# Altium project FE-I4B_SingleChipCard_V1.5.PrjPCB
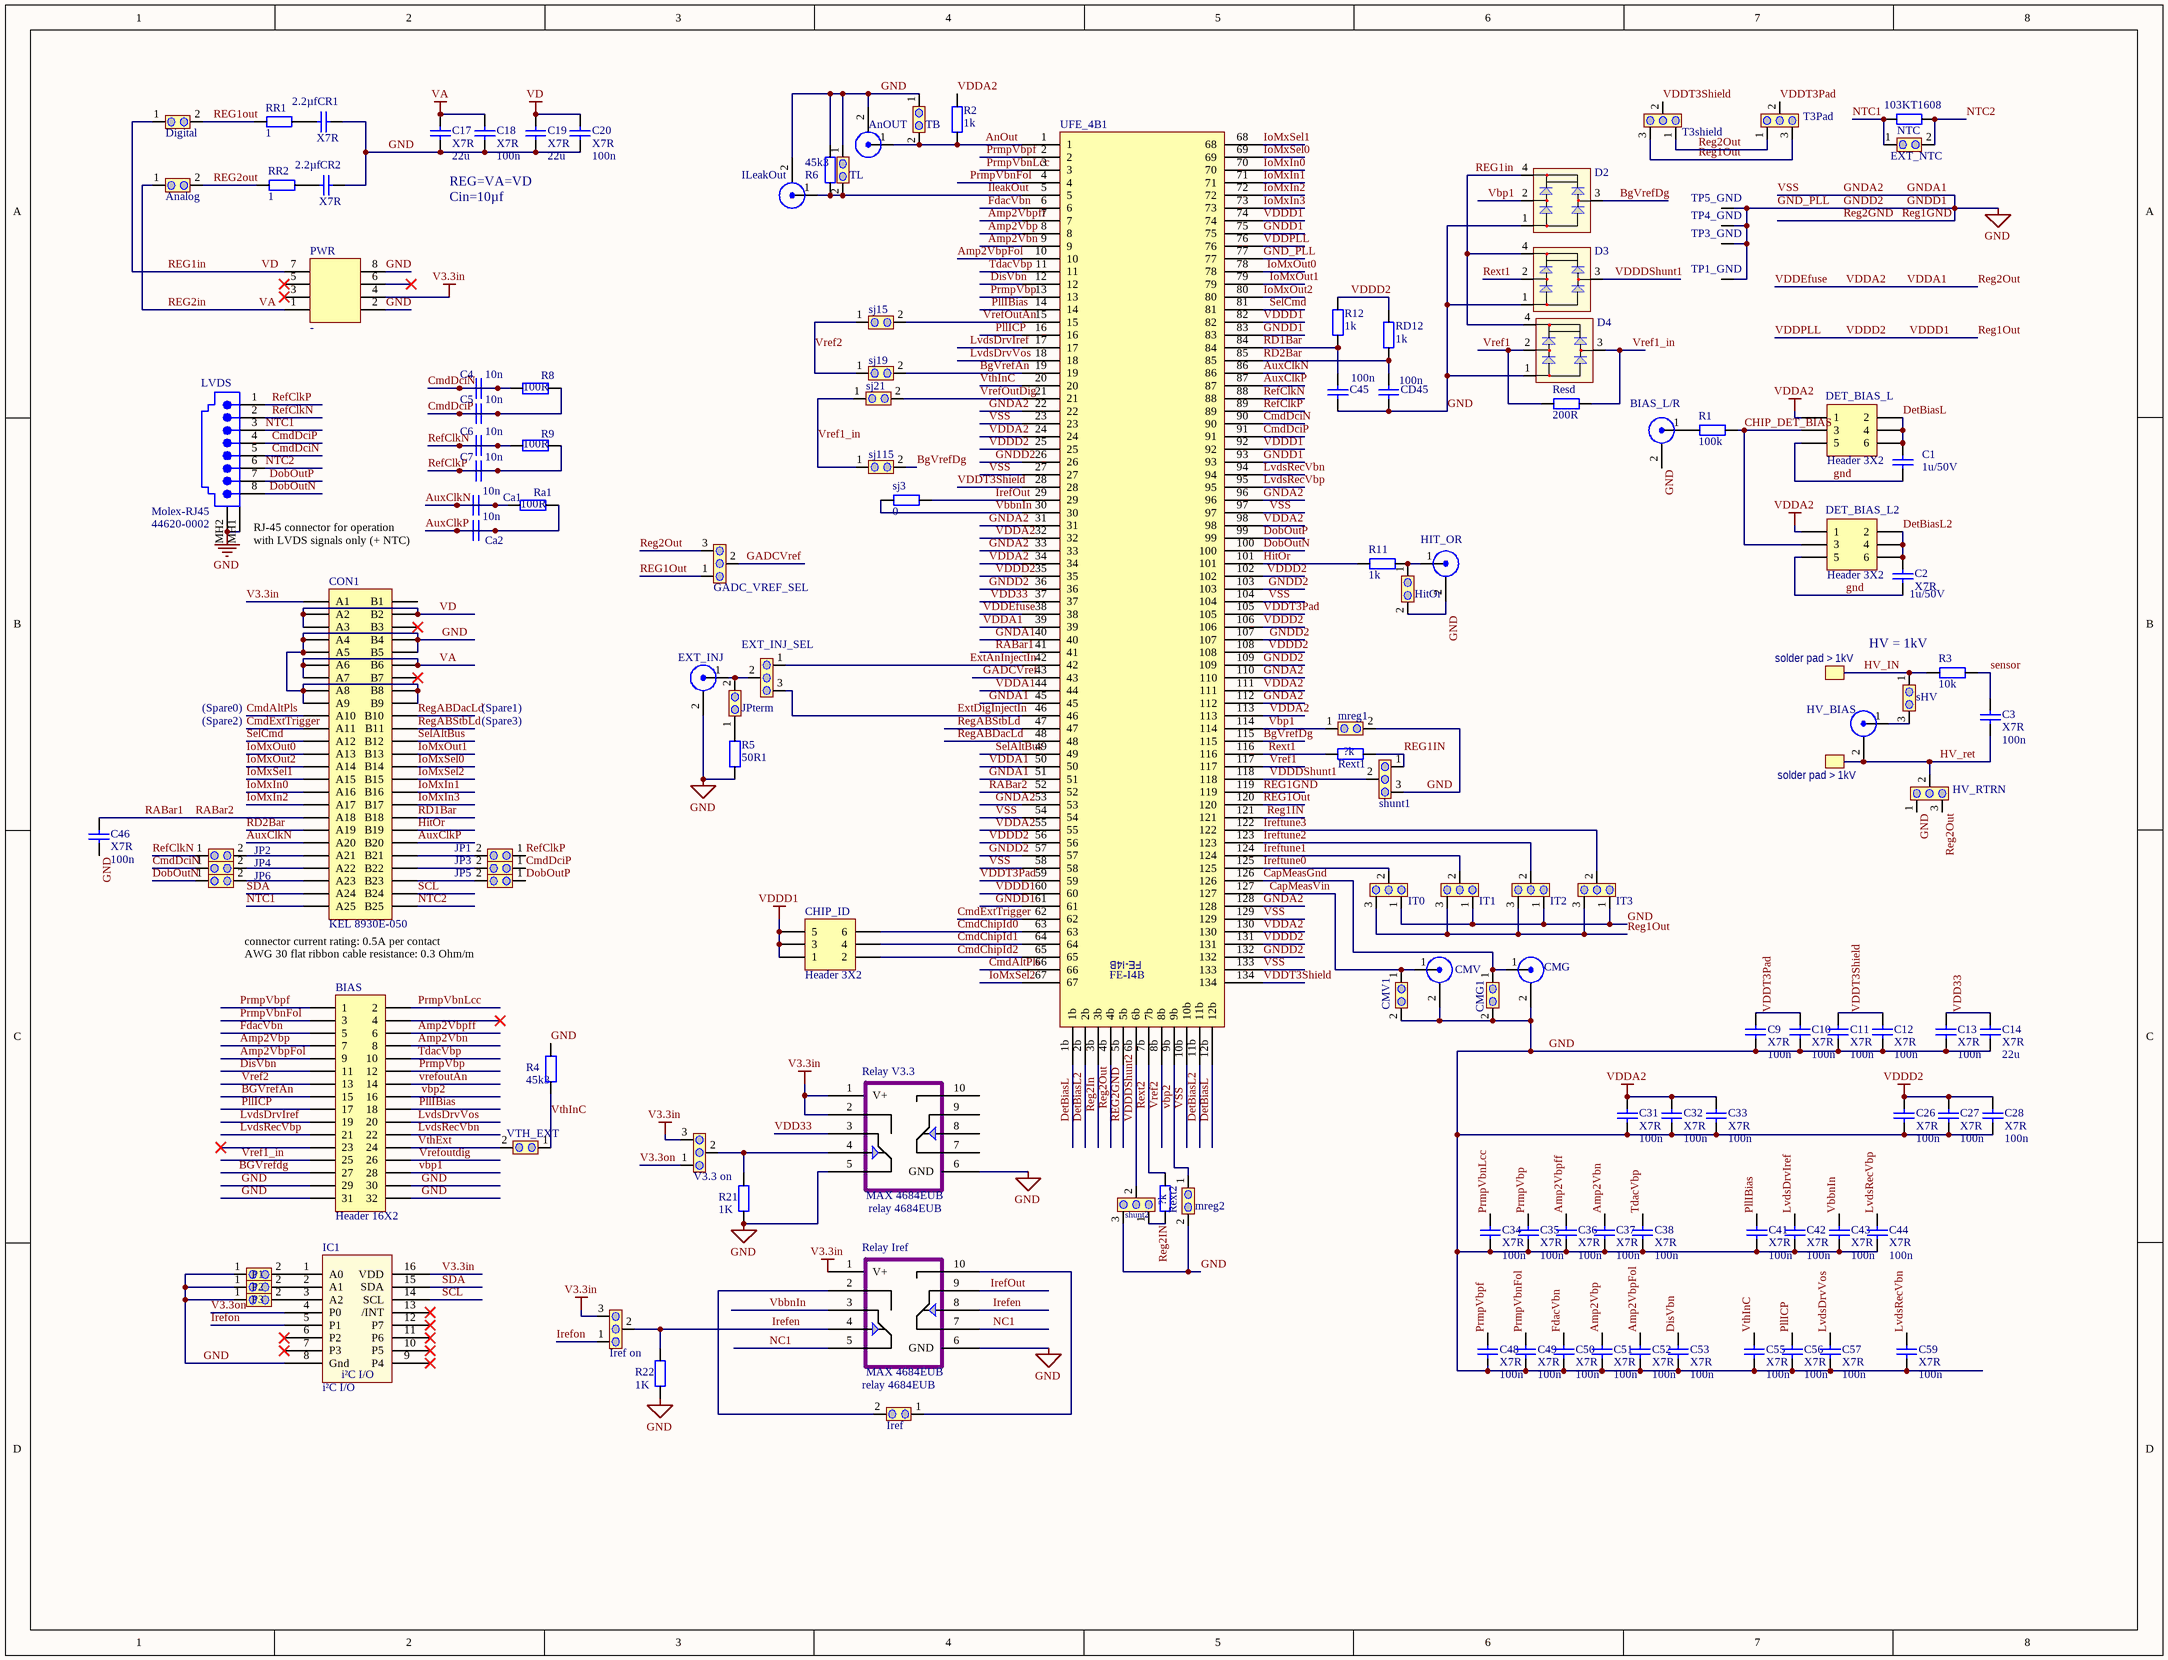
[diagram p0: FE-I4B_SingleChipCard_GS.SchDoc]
1 sheet, 136 parts. Net scope: global (net labels, ports and power ports of the same name join across sheets).
Board file: FE-I4B_SingleChipCard_V1.5.PcbDoc

## Sheet FE-I4B_SingleChipCard_GS.SchDoc: Single Chip Card
size 431 x 330 mm; CheckedBy: Laura Gonella,; Author: A.Eyring; DrawnBy: A.Eyring; Organization: SILAB; Address1: Physikalisches Institut; Address2: Universitδt Bonn; Address3: Nuίallee 12; Address4: 53115 Bonn; Revision: Rev. 1.0; SheetNumber: 1; SheetTotal: 3; Project: FE-I4B

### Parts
Analog  Jumper, 1x2  [CON 1x2 std]  (value not drawn)
AnOUT  LEMO Connector  [LEMO]  (value not drawn)
BIAS  Header 16X2  [HDR2X16]
BIAS_L/R  LEMO Connector  [LEMO]  (value not drawn)
C1  value 1u/50V  [C0805_imp_L]  (hidden comment: X7R)
C2  X7R  value 1u/50V  [C0805_imp_L]
C3  X7R  value 100n  [C5750_met_L]
C4  value 10n  [C0603_imp_L]  (hidden comment: X7R)
C5  value 10n  [C0603_imp_L]  (hidden comment: X7R)
C6  value 10n  [C0603_imp_L]  (hidden comment: X7R)
C7  value 10n  [C0603_imp_L]  (hidden comment: X7R)
C9  X7R  value 100n  [C0603_imp_L]
C10  X7R  value 100n  [C0603_imp_L]
C11  X7R  value 100n  [C0603_imp_L]
C12  X7R  value 100n  [C0603_imp_L]
C13  X7R  value 100n  [C0603_imp_L]
C14  X7R  value 22u  [C0805_imp_L]
C17  X7R  value 22u  [C0805_imp_L]
C18  X7R  value 100n  [C0603_imp_L]
C19  X7R  value 22u  [C0805_imp_L]
C20  X7R  value 100n  [C0603_imp_L]
C26  X7R  value 100n  [C0603_imp_L]
C27  X7R  value 100n  [C0603_imp_L]
C28  X7R  value 100n  [C0603_imp_L]
C31  X7R  value 100n  [C0603_imp_L]
C32  X7R  value 100n  [C0603_imp_L]
C33  X7R  value 100n  [C0603_imp_L]
C34  X7R  value 100n  [C0603_imp_L]
C35  X7R  value 100n  [C0603_imp_L]
C36  X7R  value 100n  [C0603_imp_L]
C37  X7R  value 100n  [C0603_imp_L]
C38  X7R  value 100n  [C0603_imp_L]
C41  X7R  value 100n  [C0603_imp_L]
C42  X7R  value 100n  [C0603_imp_L]
C43  X7R  value 100n  [C0603_imp_L]
C44  X7R  value 100n  [C0603_imp_L]
C45  value 100n  [C0603_imp_L]  (hidden comment: X7R)
C46  X7R  value 100n  [C0603_imp_L]
C48  X7R  value 100n  [C0603_imp_L]
C49  X7R  value 100n  [C0603_imp_L]
C50  X7R  value 100n  [C0603_imp_L]
C51  X7R  value 100n  [C0603_imp_L]
C52  X7R  value 100n  [C0603_imp_L]
C53  X7R  value 100n  [C0603_imp_L]
C55  X7R  value 100n  [C0603_imp_L]
C56  X7R  value 100n  [C0603_imp_L]
C57  X7R  value 100n  [C0603_imp_L]
C59  X7R  value 100n  [C0603_imp_L]
Ca1  value 10n  [C0603_imp_L]  (hidden comment: X7R)
Ca2  value 10n  [C0603_imp_L]  (hidden comment: X7R)
CD45  value 100n  [C0603_imp_L]  (hidden comment: X7R)
CHIP_ID  Header 3X2  [HDR2X3]
CMG  LEMO Connector  [LEMO]  (value not drawn)
CMG1  Jumper, 1x2  [CON 1x2 std]  (value not drawn)
CMV  LEMO Connector  [LEMO]  (value not drawn)
CMV1  Jumper, 1x2  [CON 1x2 std]  (value not drawn)
CON1  Type_1: KEL 8930E-050  [Kel_Connector 2x25; SMT]  (hidden comment: KEL 8930E)
CR1  X7R  value 2.2µf  [C0603_imp_L]
CR2  X7R  value 2.2µf  [C0603_imp_L]
D2  Molex 2X2  [SOT143M]  (value not drawn)
D3  Molex 2X2  [SOT143M]  (value not drawn)
D4  Molex 2X2  [SOT143M]  (value not drawn)
DET_BIAS_L  Header 3X2  [HDR2X3]
DET_BIAS_L2  Header 3X2  [HDR2X3]
Digital  Jumper, 1x2  [CON 1x2 std]  (value not drawn)
EXT_INJ  LEMO Connector  [LEMO]  (value not drawn)
EXT_INJ_SEL  Selector Jumper  [HDR 1x3]  (value not drawn)
EXT_NTC  Jumper, 1x2  [CON 1x2 std]  (value not drawn)
GADC_VREF_SEL  Selector Jumper  [HDR 1x3]  (value not drawn)
HIT_OR  LEMO Connector  [LEMO]  (value not drawn)
HitOr  Jumper, 1x2  [CON 1x2 std]  (value not drawn)
HV_BIAS  LEMO Connector  [LEMO]  (value not drawn)
HV_RTRN  Selector Jumper  [HDR 1x3]  (value not drawn)
IC1  i²C I/O  [DW016_M]
ILeakOut  LEMO Connector  [LEMO]  (value not drawn)
Iref  Jumper, 1x2  [CON 1x2 std]  (value not drawn)
Iref_on  Selector Jumper  [HDR 1x3]  (value not drawn)
IT0  Selector Jumper  [HDR 1x3]  (value not drawn)
IT1  Selector Jumper  [HDR 1x3]  (value not drawn)
IT2  Selector Jumper  [HDR 1x3]  (value not drawn)
IT3  Selector Jumper  [HDR 1x3]  (value not drawn)
JP1  Jumper, 1x2  [Lφtjumper 1x2 - small]  (value not drawn)
JP2  Jumper, 1x2  [Lφtjumper 1x2 - small]  (value not drawn)
JP3  Jumper, 1x2  [Lφtjumper 1x2 - small]  (value not drawn)
JP4  Jumper, 1x2  [Lφtjumper 1x2 - small]  (value not drawn)
JP5  Jumper, 1x2  [Lφtjumper 1x2 - small]  (value not drawn)
JP6  Jumper, 1x2  [Lφtjumper 1x2 - small]  (value not drawn)
JPterm  Jumper, 1x2  [CON 1x2 std]  (value not drawn)
LVDS  Comment_1: Molex-RJ45  [44620-0002]  (hidden comment: -)
mreg1  Jumper, 1x2  [CON 1x2 std]  (value not drawn)
mreg2  Jumper, 1x2  [CON 1x2 std]  (value not drawn)
NTC  value 103KT1608  [R0603_imp_L]  (hidden comment: R?)
P1  Jumper, Solderbridge 1x2  [Lφtjumper 1x2]  (value not drawn)
P2  Jumper, Solderbridge 1x2  [Lφtjumper 1x2]  (value not drawn)
P3  Jumper, Solderbridge 1x2  [Lφtjumper 1x2]  (value not drawn)
PWR  -  [MOLEX SD-5569]
R1  value 100k  [R0603_imp_L]  (hidden comment: R?)
R2  value 1k  [R0603_imp_L]  (hidden comment: R?)
R3  value 10k  [R1206_imp_L]  (hidden comment: R?)
R4  value 45k3  [R0603_imp_L]  (hidden comment: R?)
R5  value 50R1  [R0603_imp_L]  (hidden comment: R?)
R6  value 45k3  [R0603_imp_L]  (hidden comment: R?)
R8  value 100R  [R0603_imp_L]  (hidden comment: R?)
R9  value 100R  [R0603_imp_L]  (hidden comment: R?)
R11  value 1k  [R0603_imp_L]  (hidden comment: R?)
R12  value 1k  [R0603_imp_L]  (hidden comment: R?)
R21  value 1K  [R0603_imp_L]  (hidden comment: R?)
R22  value 1K  [R0603_imp_L]  (hidden comment: R?)
Ra1  value 100R  [R0603_imp_L]  (hidden comment: R?)
RD12  value 1k  [R0603_imp_L]  (hidden comment: R?)
Relay_Iref  relay 4684EUB  [UMAX10]
Relay_V3.3  relay 4684EUB  [UMAX10]
Resd  value 200R  [R0603_imp_L]  (hidden comment: R?)
Rext1  value ?k  [R0603_imp_L]  (hidden comment: R?)
Rext2  value ?k  [R0603_imp_L]  (hidden comment: R?)
RR1  value 1  [R0603_imp_L]  (hidden comment: R?)
RR2  value 1  [R0603_imp_L]  (hidden comment: R?)
shunt1  Jumper, Solderbridge 1x3  [solderjumper3]  (value not drawn)
shunt2  Jumper, Solderbridge 1x3  [solderjumper3]  (value not drawn)
sHV  Wire Bridge  [HDR 1;3]  (value not drawn)
sj3  value 0  [R0603_imp_L]  (hidden comment: R?)
sj15  Jumper, Solderbridge 1x2  [Lφtjumper 1x2 - small]  (value not drawn)
sj19  Jumper, Solderbridge 1x2  [Lφtjumper 1x2 - small]  (value not drawn)
sj21  Jumper, Solderbridge 1x2  [Lφtjumper 1x2 - small]  (value not drawn)
sj115  Jumper, Solderbridge 1x2  [Lφtjumper 1x2 - small]  (value not drawn)
T3Pad  Jumper, Solderbridge 1x3  [solderjumper3]  (value not drawn)
T3shield  Jumper, Solderbridge 1x3  [solderjumper3]  (value not drawn)
TB  Jumper, 1x2  [CON 1x2 std]  (value not drawn)
TL  Jumper, 1x2  [CON 1x2 std]  (value not drawn)
TP1_GND  Test-Point  [TEST_POINT]  (value not drawn)
TP3_GND  Test-Point  [TEST_POINT]  (value not drawn)
TP4_GND  Test-Point  [TEST_POINT]  (value not drawn)
TP5_GND  Test-Point  [TEST_POINT]  (value not drawn)
UFE_4B1  FE-I4B  [FE-I4B_PCB design]
V3.3_on  Selector Jumper  [HDR 1x3]  (value not drawn)
VTH_EXT  Jumper, Solderbridge 1x2  [Lφtjumper 1x2 - small]  (value not drawn)

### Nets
GND: AnOUT.2 BIAS.29 BIAS.30 BIAS.31 BIAS.32 BIAS_L/R.2 C1.2 C2.2 C9.2 C10.2 C11.2 C12.2 C13.2 C14.2 C17.2 C18.2 C19.2 C20.2 C26.2 C27.2 C28.2 C31.2 C32.2 C33.2 C34.2 C35.2 C36.2 C37.2 C38.2 C41.2 C42.2 C43.2 C44.2 C45.2 C46.2 C48.2 C49.2 C50.2 C51.2 C52.2 C53.2 C55.2 C56.2 C57.2 C59.2 CD45.2 CMG.2 CMG1.2 CMV.2 CMV1.2 CON1.7(A4) CON1.8(B4) CON1.9(A5) CON1.10(B5) CON1.15(A8) CON1.16(B8) CON1.17(A9) CON1.18(B9) CR1.2 CR2.2 D2.1 D3.1 D4.1 DET_BIAS_L.5 DET_BIAS_L2.5 EXT_INJ.2 HIT_OR.2 HitOr.2 HV_RTRN.1 IC1.8(Gnd) ILeakOut.2 IT0.1 IT1.1 IT2.1 IT3.1 LVDS.MH1(Shield) LVDS.MH2(Shield) mreg1.2 mreg2.2 P1.1 P2.1 P3.1 PWR.2 PWR.8 R4.2 R5.1 R6.2 R21.1 R22.1 Relay_Iref.6(GND) Relay_V3.3.5(NC1) Relay_V3.3.6(GND) shunt1.3 shunt2.3 TB.1 TL.1 TP1_GND.1 TP3_GND.1 TP4_GND.1 TP5_GND.1 UFE_4B1.5b UFE_4B1.10b UFE_4B1.22 UFE_4B1.23 UFE_4B1.26 UFE_4B1.27 UFE_4B1.31 UFE_4B1.33 UFE_4B1.36 UFE_4B1.40 UFE_4B1.45 UFE_4B1.51 UFE_4B1.53 UFE_4B1.54 UFE_4B1.57 UFE_4B1.58 UFE_4B1.61 UFE_4B1.75 UFE_4B1.77 UFE_4B1.83 UFE_4B1.93 UFE_4B1.96 UFE_4B1.97 UFE_4B1.103 UFE_4B1.104 UFE_4B1.107 UFE_4B1.109 UFE_4B1.110 UFE_4B1.112 UFE_4B1.119 UFE_4B1.128 UFE_4B1.129 UFE_4B1.132 UFE_4B1.133  [also labelled GND_PLL, GNDA1, GNDA2, GNDD1, GNDD2, REG1GND, REG2GND, VSS]
Reg1IN: C19.1 C20.1 CON1.3(A2) CON1.4(B2) CON1.5(A3) D2.4 D3.4 D4.4 Digital.1 PWR.7 Rext1.1 shunt1.1 UFE_4B1.121  [also labelled VD]
REG1Out: C26.1 C27.1 C28.1 CHIP_ID.1 CHIP_ID.3 CHIP_ID.5 Digital.2 GADC_VREF_SEL.1 IT0.3 IT1.3 IT2.3 IT3.3 R12.2 RD12.2 RR1.2 T3Pad.3 T3shield.3 UFE_4B1.25 UFE_4B1.35 UFE_4B1.56 UFE_4B1.60 UFE_4B1.74 UFE_4B1.76 UFE_4B1.82 UFE_4B1.92 UFE_4B1.102 UFE_4B1.106 UFE_4B1.108 UFE_4B1.120 UFE_4B1.131  [also labelled VDDD1, VDDD2, VDDPLL]
Reg2In: Analog.1 C17.1 C18.1 CON1.11(A6) CON1.12(B6) CON1.13(A7) PWR.1 Rext2.1 shunt2.1 UFE_4B1.3b  [also labelled VA]
Reg2Out: Analog.2 C31.1 C32.1 C33.1 DET_BIAS_L.1 DET_BIAS_L2.1 GADC_VREF_SEL.3 HV_RTRN.3 R2.2 RR2.2 T3Pad.1 T3shield.1 UFE_4B1.4b UFE_4B1.24 UFE_4B1.32 UFE_4B1.34 UFE_4B1.38 UFE_4B1.39 UFE_4B1.44 UFE_4B1.50 UFE_4B1.55 UFE_4B1.98 UFE_4B1.111 UFE_4B1.113 UFE_4B1.130  [also labelled VDDA1, VDDA2, VDDEfuse]
V3.3in: CON1.1(A1) IC1.16(VDD) Iref_on.3 PWR.4 Relay_Iref.1(V+) Relay_V3.3.1(V+) Relay_V3.3.2(NO1) V3.3_on.3
Amp2Vbn: BIAS.8 C37.1 UFE_4B1.9
Amp2Vbp: BIAS.7 C51.1 UFE_4B1.8
Amp2Vbpff: BIAS.6 C36.1 UFE_4B1.7
Amp2VbpFol: BIAS.9 C52.1 UFE_4B1.10
AnOut: AnOUT.1 R2.1 TB.2 UFE_4B1.1
AuxClkN: Ca1.1 Ca1.2 CON1.39(A20) Ra1.2 UFE_4B1.86
AuxClkP: Ca2.1 Ca2.2 CON1.40(B20) Ra1.1 UFE_4B1.87
BgVrefAn: BIAS.15 sj19.2 UFE_4B1.19
BgVrefDg: BIAS.27 D2.3 sj115.2 UFE_4B1.115
CapMeasGnd: CMG.1 CMG1.1 UFE_4B1.126
CapMeasVin: CMV.1 CMV1.1 UFE_4B1.127
CHIP_DET_BIAS: DET_BIAS_L.3 DET_BIAS_L2.3 R1.2
CmdAltPls: CON1.19(A10) UFE_4B1.66
CmdChipId0: CHIP_ID.6 UFE_4B1.63
CmdChipId1: CHIP_ID.4 UFE_4B1.64
CmdChipId2: CHIP_ID.2 UFE_4B1.65
CmdDciN: C4.1 C4.2 JP4.1 LVDS.5 R8.2 UFE_4B1.90
CmdDciP: C5.1 C5.2 JP3.1 LVDS.4 R8.1 UFE_4B1.91
CmdExtTrigger: CON1.21(A11) UFE_4B1.62
DetBiasL: C1.1 DET_BIAS_L.2 DET_BIAS_L.4 DET_BIAS_L.6 UFE_4B1.1b UFE_4B1.12b
DetBiasL2: C2.1 DET_BIAS_L2.2 DET_BIAS_L2.4 DET_BIAS_L2.6 UFE_4B1.2b UFE_4B1.11b
DisVbn: BIAS.11 C53.1 UFE_4B1.12
DobOutN: JP6.1 LVDS.8 UFE_4B1.100
DobOutP: JP5.1 LVDS.7 UFE_4B1.99
ExtAnInjectIn: EXT_INJ_SEL.1 UFE_4B1.42
ExtDigInjectIn: EXT_INJ_SEL.3 UFE_4B1.46
FdacVbn: BIAS.5 C50.1 UFE_4B1.6
GADCVref: GADC_VREF_SEL.2 UFE_4B1.43
HitOr: CON1.38(B19) R11.2 UFE_4B1.101
HV_IN: R3.1 sHV.1
HV_ret: C3.2 HV_BIAS.2 HV_RTRN.2
IleakOut: ILeakOut.1 R6.1 TL.2 UFE_4B1.5
IoMxIn0: CON1.31(A16) UFE_4B1.70
IoMxIn1: CON1.32(B16) UFE_4B1.71
IoMxIn2: CON1.33(A17) UFE_4B1.72
IoMxIn3: CON1.34(B17) UFE_4B1.73
IoMxOut0: CON1.25(A13) UFE_4B1.78
IoMxOut1: CON1.26(B13) UFE_4B1.79
IoMxOut2: CON1.27(A14) UFE_4B1.80
IoMxSel0: CON1.28(B14) UFE_4B1.69
IoMxSel1: CON1.29(A15) UFE_4B1.68
IoMxSel2: CON1.30(B15) UFE_4B1.67
Irefen: Iref_on.2 R22.2 Relay_Iref.4(IN1) Relay_Iref.8(IN2)
Irefon: IC1.5(P1) Iref_on.1
IrefOut: Relay_Iref.9(com2) sj3.1 UFE_4B1.29
Ireftune0: IT0.2 UFE_4B1.125
Ireftune1: IT1.2 UFE_4B1.124
Ireftune2: IT2.2 UFE_4B1.123
Ireftune3: IT3.2 UFE_4B1.122
LvdsDrvIref: BIAS.19 C42.1 UFE_4B1.17
LvdsDrvVos: BIAS.20 C57.1 UFE_4B1.18
LvdsRecVbn: BIAS.22 C59.1 UFE_4B1.94
LvdsRecVbp: BIAS.21 C44.1 UFE_4B1.95
NC1: Relay_Iref.5(NC1) Relay_Iref.7(NC2)
NTC1: CON1.49(A25) EXT_NTC.1 LVDS.3 NTC.2
NTC2: CON1.50(B25) EXT_NTC.2 LVDS.6 NTC.1
PllIBias: BIAS.18 C41.1 UFE_4B1.14
PllICP: BIAS.17 C56.1 UFE_4B1.16
PrmpVbnFol: BIAS.3 C49.1 UFE_4B1.4
PrmpVbnLcc: BIAS.2 C34.1 UFE_4B1.3
PrmpVbp: BIAS.12 C35.1 UFE_4B1.13
PrmpVbpf: BIAS.1 C48.1 UFE_4B1.2
RABar1: C46.1 CON1.35(A18) UFE_4B1.41 UFE_4B1.52  [also labelled RABar2]
RD1Bar: C45.1 CON1.36(B18) R12.1 UFE_4B1.84
RD2Bar: CD45.1 CON1.37(A19) RD12.1 UFE_4B1.85
RefClkN: C6.1 C6.2 JP2.1 LVDS.2 R9.2 UFE_4B1.88
RefClkP: C7.1 C7.2 JP1.1 LVDS.1 R9.1 UFE_4B1.89
RegABDacLd: CON1.20(B10) UFE_4B1.48
RegABStbLd: CON1.22(B11) UFE_4B1.47
Rext1: D3.2 Rext1.2 UFE_4B1.116
Rext2: Rext2.2 UFE_4B1.7b
SCL: CON1.48(B24) IC1.14(SCL)
SDA: CON1.47(A24) IC1.15(SDA)
SelAltBus: CON1.24(B12) UFE_4B1.49
SelCmd: CON1.23(A12) UFE_4B1.81
sensor: C3.1 R3.2
TdacVbp: BIAS.10 C38.1 UFE_4B1.11
V3.3on: IC1.4(P0) V3.3_on.1
VbbnIn: C43.1 Relay_Iref.3(com1) sj3.2 UFE_4B1.30
Vbp1: BIAS.28 D2.2 mreg1.1 UFE_4B1.114
vbp2: BIAS.16 mreg2.1 UFE_4B1.9b
VDD33: C13.1 C14.1 Relay_V3.3.3(com1) UFE_4B1.37
VDDDShunt1: D3.3 shunt1.2 UFE_4B1.118
VDDDShunt2: shunt2.2 UFE_4B1.6b
VDDT3Pad: C9.1 C10.1 T3Pad.2 UFE_4B1.59 UFE_4B1.105
VDDT3Shield: C11.1 C12.1 T3shield.2 UFE_4B1.28 UFE_4B1.134
Vref1: D4.2 Resd.1 UFE_4B1.117
Vref1_in: BIAS.25 D4.3 Resd.2 sj21.1 sj115.1
Vref2: BIAS.13 sj15.1 sj19.1 UFE_4B1.8b
VrefOutAn: BIAS.14 sj15.2 UFE_4B1.15
VrefOutDig: BIAS.26 sj21.2 UFE_4B1.21
VthExt: BIAS.24 VTH_EXT.2
VthInC: C55.1 R4.1 UFE_4B1.20 VTH_EXT.1
NetBIAS_L/R_1: BIAS_L/R.1 R1.1
NetCON1_41: CON1.41(A21) JP2.2
NetCON1_42: CON1.42(B21) JP1.2
NetCON1_43: CON1.43(A22) JP4.2
NetCON1_44: CON1.44(B22) JP3.2
NetCON1_45: CON1.45(A23) JP6.2
NetCON1_46: CON1.46(B23) JP5.2
NetCR1_1: CR1.1 RR1.1
NetCR2_1: CR2.1 RR2.1
NetEXT_INJ_1: EXT_INJ.1 EXT_INJ_SEL.2 JPterm.2
NetHIT_OR_1: HIT_OR.1 HitOr.1 R11.1
NetHV_BIAS_1: HV_BIAS.1 sHV.3
NetIC1_1: IC1.1(A0) P1.2
NetIC1_2: IC1.2(A1) P2.2
NetIC1_3: IC1.3(A2) P3.2
NetIref_1: Iref.1 Relay_Iref.10(NO2)
NetIref_2: Iref.2 Relay_Iref.2(NO1)
NetJPterm_1: JPterm.1 R5.2
NetR21_2: R21.2 Relay_V3.3.4(IN1) V3.3_on.2

Not connected (* = marked no-connect by the designer): BIAS 4* 23*; CON1 2(B1) 6(B3)* 14(B7)*; IC1 6(P2)* 7(P3)* 9(P4)* 10(P5)* 11(P6)* 12(P7)* 13(/INT)*; PWR 3* 5* 6*; Relay_V3.3 7(NC2) 8(IN2) 9(com2) 10(NO2)

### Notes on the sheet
- REG=VA=VD
- Cin=10µf
- (near LVDS) RJ-45 connector for operation with LVDS signals only (+ NTC)
- solder pad > 1kV
- HV = 1kV
- (Spare0)
- (Spare2)
- (Spare1)
- (Spare3)
- connector current rating: 0.5A per contact
  AWG 30 flat ribbon cable resistance: 0.3 Ohm/m

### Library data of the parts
Analog = JUMPER 1X2S: KEL  8930E-050-178MS-F  - 8930E 50 pin PCB SMD connector; Manufacturer: MOLEX
AnOUT BIAS_L/R CMG CMV EXT_INJ HIT_OR HV_BIAS ILeakOut = LEMO coax: LEMO - EPL.00.250.NTN - SOCKET, 00, RIGHT ANGLE, PCB, 50OHM
BIAS = Header 16X2: Header, 16-Pin, Dual row; Manufacturer: JPR Electronics; Manufacturer Part Number: 710-316; Class: Connector; Comment_1: Cut down to size 32; Value: Connector
C1 C2 = C: TDK - CGA4J3X7R1H105M125AE - CAPACITOR, 1UF, 0805, 50V, +/-20%; Constraints: 6.3V; Class: Passive; Type_1: SMD Chip Capacitor
C3 = C: AVX - 2225AC104KAZ1A - CAPACITOR CERAMIC 0.1UF 1000V, X7R, 10%, 2225; Constraints: 1KV; Class: Passive; Type_1: SMD Chip Capacitor
C4-C7 Ca1 Ca2 = C: AVX - 06035C103JAT2A - CAP MLCC, 0.01UF, 50V, X7R, 5%, 0603; Constraints: 6.3V; Comment_1: Minimum order 10; Class: Passive; Type_1: SMD Chip Capacitor
C9-C13 C18 C20 C26-C28 C31-C38 C41-C46 C48-C53 C55-C57 C59 CD45 = C: AVX - 0603YC104K4T4A - CAP, CERAMIC, 0.1UF, 16V, X7R, 0603; Constraints: 6.3V; Class: Passive; Type_1: SMD Chip Capacitor
C14 C17 C19 = C: AVX - 0805ZD226MAT2A - CAP MLCC, 22UF, 10V, X5R, 20%, 0805; Constraints: 6.3V; Comment_1: Minimum order 10 order only 10 per <= 3 boards; Class: Passive; Type_1: SMD Chip Capacitor
CHIP_ID DET_BIAS_L DET_BIAS_L2 = Header 3X2: SAMTEC - TLW-103-05-G-D - HEADER, 2.54MM, DUAL, 6WAY; Class: Connector; Value: Connector
CMG1 CMV1 Digital EXT_NTC HitOr Iref JP1-JP6 JPterm mreg1 mreg2 TB TL = JUMPER 1X2S: MOLEX - 22-03-2021 - HEADER, THT, VERTICAL, 2.54MM, 2WAY; Class: Connector; Value: Connector
CON1 = CON KEL 8930E: KEL  8930E-050-178MS-F  - 8930E 50 pin PCB SMD connector
CR1 CR2 = C: MURATA - GRM188R71A225KE15D - CAP, CERAMIC, 2.2UF, 10V, X7R, 0603; Constraints: 6.3V; Class: Passive; Type_1: SMD Chip Capacitor
D2-D4 = CM1213A: ESD Suppressors 2-ch. 8KV/1pF Ultra; Manufacturer: ON Semiconductor; Manufacturer Part Number: CM1213A-02SR; Class: Passive; Value: ESD Diode
EXT_INJ_SEL GADC_VREF_SEL HV_RTRN Iref_on IT0-IT3 V3.3_on = JUMPER 1X3S: SAMTEC - TSW-103-07-F-S - HEADER, 2.54MM, THT VERT, 3WAY; Class: Connector; Comment_1: Minimun order quantity 10
IC1 = PCF8574: NXP - PCF8574T/3,518 - IC, I/O EXPANDER, 8BIT, SOIC16; Class: Passive
LVDS = RJ-45 Buchse: Modular Jack, Right Angle RJ-45, Low Profile, Inverted, with all Panel Grounding Tabs, Shielded with RJ-11 Keepout Feature; Manufacturer: MOLEX; Class: Connector; Value: 1551505
NTC = R: Thermistor; Manufacturer: Semitec; Manufacturer Part Number: 103KT1608T-3P; Constraints: 1%; Class: Passive; Type_1: SMD Chip Resistor
P1-P3 sj15 sj19 sj21 sj115 VTH_EXT = JUMPER 1X2S: Manufacturer: none; Class: Connector; Comment_1: SolderJumper; Value: SolderJumper
PWR = MOLEX SD-5569: MOLEX 8 pin Power Connector, SD-5569
R1 = R: VISHAY DRALORIC - CRCW0603100KFKEA - RESISTOR, 100K, 0.1W, 1%, 0603, SMD; Comment_1: Minimum order 50 order only 50 per <= 50 boards; Class: Passive; Type_1: SMD Chip Resistor
R2 R11 R12 R21 R22 RD12 sj3 = R: VISHAY DRALORIC - CRCW06031K00FKEA - RESISTOR, 1K, 0.1W, 1%, 0603, SMD; Class: Passive; Type_1: SMD Chip Resistor
R3 = R: BOURNS - CR0603-JW-103ELF - RESISTOR, 10K, 0.1W, 5%; Constraints: 1%; Class: Passive; Type_1: SMD Chip Resistor
R4 R6 = R: VISHAY DRALORIC - CRCW060345K3FKEA - RESISTOR, 0603, 45K3, 1%; Comment_1: Minimum order 50 order only 50 per <= 50 boards; Class: Passive; Type_1: SMD Chip Resistor
R5 = R: VISHAY DALE - CRCW060350R0FKEA - RESISTOR, THICK FILM, 50R, 100MW, 1%; Class: Passive; Type_1: SMD Chip Resistor
R8 R9 Ra1 = R: PANASONIC - ERA3AEB101V - RESISTOR, 0603, 100R, 0.1%, 0.1W; Constraints: 1%; Class: Passive; Type_1: SMD Chip Resistor
Relay_Iref Relay_V3.3 = relay 4684EUB: .5Ohm Dual SPDT Analog IC Switch; Manufacturer: Maxim Integrated; Manufacturer Part Number: MAX4684EUB+; Class: Connector
Resd = R: PANASONIC - ERJ3EKF2000V - RESISTOR, 0603, 200R 1%, 0.1W; Comment_1: Minimum order 50 order only 50 per <= 50 boards; Class: Passive; Type_1: SMD Chip Resistor
Rext1 Rext2 = R: SMD Chip Resistor; Comment_1: Do not populate; Constraints: 1%; Class: Passive
RR1 RR2 = R: WELWYN - LRCS0603-1RFT5 - RESISTOR, 1R 1% 0603; Class: Passive; Type_1: SMD Chip Resistor
shunt1 shunt2 T3Pad T3shield = JUMPER 1X3S: Manufacturer: none; Class: Connector; Comment_1: SolderJumper; Value: SolderJumper
sHV = JUMPER 1X2S: Class: Connector; Comment_1: Do not populate
TP1_GND TP3_GND TP4_GND TP5_GND = anschluss: VERO - 20-2137 - TERMINAL, PCB, BLACK; Class: Connector; Comment_1: Pack of 100 order only 1 per <= 20 boards; Value: TEST_POINT
UFE_4B1 = FE-I4B: IBL FE-I4B; Manufacturer: none; Class: Connector; Value: FE Pad Array

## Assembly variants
Standard FEI4SingleChipCard: not fitted BIAS BIAS_L/R C1 C2 C3 C4 C5 C6 C7 C8 C21 EXT_INJ EXT_NTC HIT_OR HV_BIAS ILeakOut JGND1 JGND2 JP1 JP2 JP3 JP4 JP5 JP6 LVDS OUT1 P_VBPBUF P_VG R6 R7 Rgnd SEL_HV_RTRN SEL_IN SENSE_L SENSE_R T3_PAD T3_SHLD TEST_OUT U1 VBB_INT VbpBuf VG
